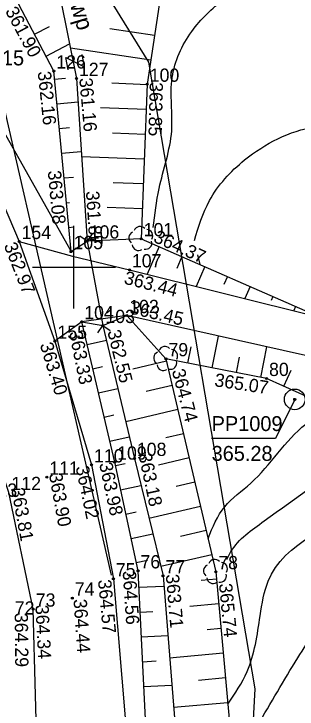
# Model space of a CAD drawing. Extents: x 4635329 to 4651863, y 5356628 to 5367582.
# Drawn here: x 4651746.37 to 4651763.49, y 5357073.31 to 5357115.3 of the extents above; entities that cross this region are included whole.
import ezdxf

# ---------------------------------------------------------------- set-up
doc = ezdxf.new("R2010")
doc.units = 0
for name, color, linetype in [('Level 1', 7, 'Continuous'), ('Level 2', 7, 'Continuous'), ('Level 20', 7, 'Continuous'), ('Level 24', 7, 'Continuous'), ('Level 36', 7, 'Continuous'), ('Level 4', 7, 'Continuous'), ('Level 44', 7, 'Continuous'), ('Level 45', 7, 'Continuous'), ('Level 46', 7, 'Continuous'), ('Level 48', 7, 'Continuous'), ('Level 50', 7, 'Continuous'), ('Level 51', 7, 'Continuous'), ('Level 53', 7, 'Continuous'), ('Level 55', 7, 'Continuous'), ('Level 60', 7, 'Continuous'), ('Level 62', 7, 'Continuous'), ('Level 63', 7, 'Continuous')]:
    doc.layers.add(name, color=color, linetype=linetype)

msp = doc.modelspace()

# ---------------------------------------------------------------- linework, layer by layer
at = {"layer": 'Level 1'}
for radius in [0.625, 0.045]:
    msp.add_circle((4651763.34, 5357092.02), radius, dxfattribs=at)
at = {"layer": 'Level 2'}
msp.add_line((4651752.271, 5357081.395), (4651734.633, 5357158.117), dxfattribs=at)
at = {"layer": 'Level 20'}
for p, q in [((4651743.25, 5357109.59), (4651746.68, 5357101.55)), ((4651746.68, 5357101.55), (4651748.85, 5357095.53)), ((4651748.85, 5357095.53), (4651751.06, 5357088.06)), ((4651751.06, 5357088.06), (4651752.38, 5357081.18)), ((4651752.38, 5357081.18), (4651753.45, 5357068.66))]:
    msp.add_line(p, q, dxfattribs=at)
for points in [[(4651729.32, 5357025.03), (4651737.42, 5357039.16), (4651742.88, 5357049.73), (4651744.63, 5357054), (4651745.586, 5357056.87), (4651746.84, 5357061.68), (4651747.431, 5357065.159), (4651747.81, 5357068.95), (4651747.54, 5357079.35), (4651746.07, 5357086.39), (4651738.98, 5357107.74), (4651737.87, 5357110.18), (4651736.57, 5357115.87), (4651735.37, 5357118.93)], [(4651746.68, 5357101.55), (4651749.905, 5357100.663), (4651753.35, 5357099.84), (4651764.92, 5357096.97), (4651771.4, 5357097), (4651779.55, 5357102.54)], [(4651781.26, 5357100.54), (4651772.78, 5357094.43), (4651763.99, 5357094.67), (4651753.19, 5357097.08), (4651750.47, 5357096.71), (4651748.85, 5357095.53)]]:
    msp.add_lwpolyline(points, dxfattribs=at)
at = {"layer": 'Level 24'}
for p, q in [((4651751.1, 5357102.017), (4651750.8, 5357101.58)), ((4651750.8, 5357101.58), (4651750.363, 5357101.88)), ((4651750.8, 5357101.58), (4651751.75, 5357096.48)), ((4651751.45, 5357096.043), (4651751.75, 5357096.48)), ((4651751.75, 5357096.48), (4651752.187, 5357096.18))]:
    msp.add_line(p, q, dxfattribs=at)
at = {"layer": 'Level 36'}
msp.add_lwpolyline([(4651763.34, 5357092.02), (4651762.187, 5357089.655), (4651758.32, 5357089.655)], dxfattribs=at)
at = {"layer": 'Level 4'}
for p, q in [((4651746.966, 5357124.583), (4651754.512, 5357112.38)), ((4651754.512, 5357112.38), (4651760.94, 5357074.531)), ((4651760.94, 5357074.531), (4651760.729, 5357071.135))]:
    msp.add_line(p, q, dxfattribs=at)
at = {"layer": 'Level 44'}
for centre in [(4651748.78, 5357111.85), (4651750.15, 5357111.4), (4651754.43, 5357111.05), (4651746.68, 5357101.55), (4651750.8, 5357101.58), (4651754.06, 5357101.72), (4651749.82, 5357100.94), (4651753.35, 5357099.84), (4651753.19, 5357097.08), (4651750.47, 5357096.71), (4651751.75, 5357096.48), (4651748.85, 5357095.53), (4651755.56, 5357094.47), (4651761.64, 5357093.28), (4651763.34, 5357092.02), (4651763.34, 5357092.02), (4651763.34, 5357092.02), (4651763.34, 5357092.02), (4651751.06, 5357088.06), (4651752.46, 5357088.23), (4651753.65, 5357088.45), (4651748.36, 5357087.32), (4651753.87, 5357081.66), (4651755.38, 5357081.36), (4651758.57, 5357081.61), (4651752.38, 5357081.18), (4651749.9, 5357080.02), (4651747.54, 5357079.35)]:
    msp.add_circle(centre, 0.04, dxfattribs=at)
at = {"layer": 'Level 46'}
msp.add_line((4651757.63, 5357100.158), (4651757.48, 5357100.746), dxfattribs=at)
for points in [[(4651754.793, 5357102.394), (4651755.147, 5357104.754), (4651755.905, 5357108.242), (4651755.935, 5357111.456), (4651757.114, 5357114.234), (4651759.084, 5357116.205), (4651762.904, 5357118.146), (4651766.694, 5357118.419), (4651770.685, 5357117.772)], [(4651757.274, 5357101.611), (4651758.19, 5357104.02), (4651760.313, 5357106.477), (4651764.557, 5357108.478), (4651771.712, 5357108.175), (4651777.847, 5357109.989), (4651782.697, 5357111.809), (4651785.064, 5357112.799)], [(4651758.1, 5357083.618), (4651759.112, 5357085.537), (4651760.688, 5357086.962), (4651764.016, 5357090.525), (4651765.592, 5357091.374), (4651765.768, 5357091.423)], [(4651759.64, 5357069.854), (4651761.095, 5357072.307), (4651763.521, 5357076.401), (4651765.794, 5357079.585), (4651768.674, 5357082.223), (4651772.525, 5357084.498), (4651783.153, 5357090.274), (4651784.378, 5357091.117)], [(4651759.237, 5357082.347), (4651759.488, 5357082.823), (4651761.489, 5357084.673), (4651767.249, 5357088.888), (4651768.341, 5357089.707), (4651768.806, 5357090.056)], [(4651759.298, 5357073.608), (4651760.465, 5357075.586), (4651761.253, 5357078.952), (4651761.739, 5357081.045), (4651768.044, 5357085.715), (4651770.337, 5357086.995)], [(4651757.599, 5357060.829), (4651759.467, 5357062.262), (4651762.013, 5357069.388), (4651763.863, 5357071.997), (4651765.651, 5357073.573), (4651768.501, 5357077.425), (4651770.563, 5357079.778)]]:
    msp.add_spline(points, degree=3, dxfattribs=at)
at = {"layer": 'Level 48'}
for p, q in [((4651747.61, 5357114.07), (4651748.515, 5357114.547)), ((4651754.864, 5357113.991), (4651752.166, 5357114.389)), ((4651748.309, 5357112.743), (4651749.729, 5357113.491)), ((4651754.645, 5357112.507), (4651749.783, 5357113.224)), ((4651748.827, 5357111.362), (4651749.48, 5357111.424)), ((4651754.429, 5357111.022), (4651752.296, 5357111.107)), ((4651748.969, 5357109.869), (4651750.243, 5357109.99)), ((4651754.369, 5357109.524), (4651751.597, 5357109.633)), ((4651749.111, 5357108.375), (4651749.727, 5357108.434)), ((4651754.31, 5357108.025), (4651752.337, 5357108.103)), ((4651749.254, 5357106.882), (4651750.442, 5357106.995)), ((4651754.251, 5357106.526), (4651750.463, 5357106.676)), ((4651749.396, 5357105.389), (4651749.968, 5357105.443)), ((4651754.191, 5357105.027), (4651752.377, 5357105.099)), ((4651749.538, 5357103.896), (4651749.723, 5357103.914)), ((4651754.132, 5357103.528), (4651752.005, 5357103.613)), ((4651749.681, 5357102.402), (4651749.998, 5357102.433)), ((4651755.151, 5357101.243), (4651754.421, 5357099.574)), ((4651756.525, 5357100.642), (4651756.211, 5357099.925)), ((4651757.899, 5357100.041), (4651757.375, 5357098.842)), ((4651759.273, 5357099.44), (4651759.062, 5357098.958)), ((4651760.648, 5357098.839), (4651760.328, 5357098.109)), ((4651762.022, 5357098.238), (4651761.914, 5357097.99)), ((4651763.396, 5357097.636), (4651763.282, 5357097.376)), ((4651758.354, 5357093.923), (4651758.73, 5357095.844)), ((4651750.794, 5357095.328), (4651751.958, 5357095.601)), ((4651756.882, 5357094.211), (4651757.074, 5357095.191)), ((4651761.298, 5357093.347), (4651761.659, 5357095.19)), ((4651759.826, 5357093.635), (4651760.01, 5357094.576)), ((4651751.137, 5357093.867), (4651751.72, 5357094.004)), ((4651755.595, 5357094.321), (4651753.553, 5357093.843)), ((4651762.69, 5357092.807), (4651763.131, 5357093.786)), ((4651755.937, 5357092.861), (4651754.359, 5357092.491)), ((4651751.48, 5357092.407), (4651752.649, 5357092.681)), ((4651751.822, 5357090.947), (4651752.408, 5357091.084)), ((4651756.279, 5357091.4), (4651753.126, 5357090.662)), ((4651752.165, 5357089.486), (4651753.34, 5357089.762)), ((4651756.62, 5357089.94), (4651755.55, 5357089.689)), ((4651752.504, 5357088.025), (4651753.098, 5357088.153)), ((4651756.962, 5357088.479), (4651755.112, 5357088.046)), ((4651752.819, 5357086.559), (4651754.047, 5357086.822)), ((4651757.304, 5357087.019), (4651756.18, 5357086.756)), ((4651757.646, 5357085.558), (4651754.533, 5357084.83)), ((4651753.133, 5357085.092), (4651753.768, 5357085.228)), ((4651753.448, 5357083.625), (4651754.759, 5357083.907)), ((4651757.988, 5357084.098), (4651756.438, 5357083.735)), ((4651758.33, 5357082.637), (4651755.244, 5357081.915)), ((4651753.763, 5357082.159), (4651754.439, 5357082.304)), ((4651758.61, 5357081.167), (4651757.678, 5357081.082)), ((4651753.919, 5357080.671), (4651755.43, 5357080.747)), ((4651758.746, 5357079.673), (4651757.005, 5357079.514)), ((4651753.994, 5357079.173), (4651754.772, 5357079.212)), ((4651758.882, 5357078.179), (4651758.048, 5357078.103)), ((4651754.069, 5357077.675), (4651755.669, 5357077.755)), ((4651759.018, 5357076.685), (4651755.778, 5357076.39)), ((4651754.144, 5357076.177), (4651754.966, 5357076.218)), ((4651759.154, 5357075.191), (4651757.526, 5357075.043)), ((4651754.218, 5357074.679), (4651755.909, 5357074.763)), ((4651759.29, 5357073.697), (4651756.018, 5357073.4))]:
    msp.add_line(p, q, dxfattribs=at)
for points in [[(4651788.23, 5357177.15), (4651778.95, 5357165), (4651774.56, 5357160.24), (4651772.52, 5357151.19), (4651770.34, 5357137.07), (4651766.1, 5357132.52), (4651760.1, 5357122.43), (4651755.24, 5357116.54), (4651754.43, 5357111.05), (4651754.06, 5357101.72), (4651764.92, 5357096.97)], [(4651739.34, 5357119.79), (4651741.917, 5357115.357), (4651743.483, 5357112.18), (4651749.82, 5357100.94)], [(4651749.82, 5357100.94), (4651748.78, 5357111.85), (4651746.64, 5357115.91), (4651743.66, 5357118.62)], [(4651749.82, 5357100.94), (4651750.8, 5357101.58)], [(4651754.06, 5357101.72), (4651750.8, 5357101.58)], [(4651750.47, 5357096.71), (4651751.75, 5357096.48), (4651753.19, 5357097.08)], [(4651753.19, 5357097.08), (4651755.56, 5357094.47)], [(4651735.13, 5357022.17), (4651743.48, 5357036.33), (4651748.947, 5357047.515), (4651754.07, 5357061.21), (4651754.52, 5357068.63), (4651753.87, 5357081.66), (4651752.46, 5357088.23), (4651750.47, 5357096.71)], [(4651751.75, 5357096.48), (4651753.65, 5357088.45), (4651755.38, 5357081.36), (4651756.43, 5357068.26), (4651755.18, 5357061.14), (4651751.39, 5357049), (4651749.99, 5357046.24), (4651744.18, 5357035.62), (4651736.09, 5357021.66)], [(4651769.53, 5357089.73), (4651761.64, 5357093.28), (4651755.56, 5357094.47), (4651758.57, 5357081.61), (4651759.7, 5357069.19), (4651757.22, 5357059.32), (4651757.66, 5357053.72), (4651755.47, 5357047.9), (4651751.39, 5357049)]]:
    msp.add_lwpolyline(points, dxfattribs=at)
at = {"layer": 'Level 50'}
for p, q in [((4651748.57, 5357119.25), (4651750.15, 5357111.4)), ((4651750.15, 5357111.4), (4651750.8, 5357101.58))]:
    msp.add_line(p, q, dxfattribs=at)
at = {"layer": 'Level 53'}
for p, q in [((4651750.637, 5357112.112), (4651750.495, 5357112.849)), ((4651749.656, 5357111.923), (4651749.514, 5357112.659)), ((4651749.514, 5357112.659), (4651750.637, 5357112.112))]:
    msp.add_line(p, q, dxfattribs=at)
at = {"layer": 'Level 55'}
for centre in [(4651754.06, 5357101.72), (4651755.56, 5357094.47), (4651758.57, 5357081.61)]:
    msp.add_circle(centre, 0.045, dxfattribs=at)
for centre, start, end in [((4651753.993, 5357102.089), 40.3488, 160.1306), ((4651753.689, 5357101.77), 112.4389, 232.0902), ((4651754.39, 5357101.898), 328.348, 88.132), ((4651754.331, 5357101.461), 256.3906, 16.0419), ((4651753.897, 5357101.382), 184.3875, 304.0933), ((4651755.493, 5357094.839), 40.3488, 160.1306), ((4651755.189, 5357094.52), 112.4389, 232.0902), ((4651755.89, 5357094.648), 328.348, 88.132), ((4651755.397, 5357094.132), 184.3875, 304.0933), ((4651755.831, 5357094.211), 256.3906, 16.0419), ((4651758.503, 5357081.979), 40.3488, 160.1306), ((4651758.199, 5357081.66), 112.4389, 232.0902), ((4651758.9, 5357081.788), 328.348, 88.132), ((4651758.841, 5357081.351), 256.3906, 16.0419), ((4651758.407, 5357081.272), 184.3875, 304.0933)]:
    msp.add_arc(centre, 0.375, start, end, dxfattribs=at)
at = {"layer": 'Level 60'}
for p, q in [((4651750, 5357097.5), (4651750, 5357102.5)), ((4651747.5, 5357100), (4651752.5, 5357100))]:
    msp.add_line(p, q, dxfattribs=at)
at = {"layer": 'Level 63'}
for centre in [(4651748.78, 5357111.85), (4651750.15, 5357111.4), (4651754.43, 5357111.05), (4651746.68, 5357101.55), (4651750.8, 5357101.58), (4651754.06, 5357101.72), (4651749.82, 5357100.94), (4651753.35, 5357099.84), (4651753.19, 5357097.08), (4651750.47, 5357096.71), (4651751.75, 5357096.48), (4651748.85, 5357095.53), (4651755.56, 5357094.47), (4651761.64, 5357093.28), (4651763.34, 5357092.02), (4651763.34, 5357092.02), (4651763.34, 5357092.02), (4651763.34, 5357092.02), (4651753.65, 5357088.45), (4651751.06, 5357088.06), (4651752.46, 5357088.23), (4651748.36, 5357087.32), (4651753.87, 5357081.66), (4651755.38, 5357081.36), (4651758.57, 5357081.61), (4651752.38, 5357081.18), (4651749.9, 5357080.02), (4651747.54, 5357079.35)]:
    msp.add_circle(centre, 0.06, dxfattribs=at)

# ---------------------------------------------------------------- texts
at = {"layer": 'Level 36'}
for s, p in [('PP1009', (4651758.32, 5357090.105)), ('365.28', (4651758.32, 5357088.305))]:
    msp.add_text(s, height=0.9, dxfattribs=at).set_placement(p)
at = {"layer": 'Level 45'}
for s, rotation, p in [('361.90', 298.0066, (4651745.82, 5357115.477)), ('362.16', 275.8916, (4651747.807, 5357111.801)), ('361.16', 275.0164, (4651750.317, 5357111.408)), ('363.85', 268.5781, (4651754.581, 5357111.186)), ('363.08', 275.2667, (4651748.414, 5357105.811)), ('361.87', 273.8613, (4651750.721, 5357104.586)), ('364.37', 335.6797, (4651754.747, 5357101.555)), ('362.97', 291.4587, (4651745.747, 5357101.319)), ('363.44', 345.5918, (4651752.975, 5357099.015)), ('363.45', 346.6851, (4651753.326, 5357097.218)), ('363.33', 281.4337, (4651749.7, 5357096.065)), ('362.55', 283.7393, (4651752.011, 5357096.121)), ('363.40', 286.8331, (4651747.927, 5357095.329)), ('364.74', 284.6414, (4651755.907, 5357093.746)), ('365.07', 351.3792, (4651758.455, 5357092.818)), ('363.18', 282.1257, (4651753.888, 5357088.687)), ('363.98', 282.1364, (4651751.515, 5357088.129)), ('364.02', 281.7976, (4651750.095, 5357087.93)), ('363.90', 280.3241, (4651748.482, 5357087.497)), ('363.81', 280.4303, (4651746.199, 5357086.616)), ('364.56', 273.8078, (4651752.94, 5357081.653)), ('363.71', 274.9104, (4651755.547, 5357081.433)), ('364.57', 275.3131, (4651751.45, 5357081.106)), ('365.74', 275.5132, (4651758.761, 5357080.873)), ('364.44', 273.9236, (4651749.972, 5357079.941)), ('364.34', 272.9209, (4651747.665, 5357079.588)), ('364.29', 270.6484, (4651746.414, 5357079.118))]:
    msp.add_text(s, height=0.8, rotation=rotation, dxfattribs=at).set_placement(p)
at = {"layer": 'Level 51'}
msp.add_text('wp', height=1, rotation=286.7595, dxfattribs=at).set_placement((4651749.752, 5357115.861))
at = {"layer": 'Level 62'}
msp.add_text(' 15', height=0.9, dxfattribs=at).set_placement((4651745.31, 5357112.19))
at = {"layer": 'Level 63'}
for s, p in [('126', (4651748.93, 5357112)), ('127', (4651750.3, 5357111.55)), ('100', (4651754.58, 5357111.2)), ('154', (4651746.83, 5357101.7)), ('106', (4651750.95, 5357101.73)), ('101', (4651754.21, 5357101.87)), ('105', (4651749.97, 5357101.09)), ('107', (4651753.5, 5357099.99)), ('102', (4651753.34, 5357097.23)), ('104', (4651750.62, 5357096.86)), ('103', (4651751.9, 5357096.63)), ('155', (4651749, 5357095.68)), ('79', (4651755.71, 5357094.62)), ('80', (4651761.79, 5357093.43)), ('108', (4651753.8, 5357088.6)), ('110', (4651751.21, 5357088.21)), ('109', (4651752.61, 5357088.38)), ('111', (4651748.51, 5357087.47)), ('112', (4651746.22, 5357086.54)), ('113', (4651744.78, 5357086.14)), ('76', (4651754.02, 5357081.81)), ('77', (4651755.53, 5357081.51)), ('78', (4651758.72, 5357081.76)), ('75', (4651752.53, 5357081.33)), ('74', (4651750.05, 5357080.17)), ('73', (4651747.69, 5357079.5)), ('72', (4651746.42, 5357079.02))]:
    msp.add_text(s, height=0.8, dxfattribs=at).set_placement(p)

doc.saveas('drawing.dxf')
